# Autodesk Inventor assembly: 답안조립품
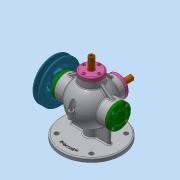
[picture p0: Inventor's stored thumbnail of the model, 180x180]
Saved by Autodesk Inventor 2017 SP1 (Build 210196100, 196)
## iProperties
Part Number: 답안조립품
Material: 일반
Document SubType Name: Assembly
Designer: MRC
Mass: 3733.58 g
Surface Area: 2584.17 cm^2
Volume: 938.795 cm^3
Density: 3.97699 g/cm^3
Author: MRC
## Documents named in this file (17)
- C:\Users\MRC\Desktop\620909V1003\답안조립품.iam
- C:\Users\MRC\Desktop\620909V1003\본체.ipt
- C:\Users\MRC\Desktop\620909V1003\V-벨트풀리.ipt
- C:\Users\MRC\Desktop\620909V1003\너트-M8x1.ipt
- C:\Users\MRC\Desktop\620909V1003\뒤커버.ipt
- C:\Users\MRC\Desktop\620909V1003\베어링- 6202.ipt
- C:\Users\MRC\Desktop\620909V1003\본체커버.ipt
- C:\Users\MRC\Desktop\620909V1003\볼트 M4x0.7.ipt
- C:\Users\MRC\Desktop\620909V1003\슬라이드 커버.ipt
- C:\Users\MRC\Desktop\620909V1003\슬라이드.ipt
- C:\Users\MRC\Desktop\620909V1003\앞커버.ipt
- C:\Users\MRC\Desktop\620909V1003\오일실.ipt
- C:\Users\MRC\Desktop\620909V1003\와셔 8x17.ipt
- C:\Users\MRC\Desktop\620909V1003\축.ipt
- C:\Users\MRC\Desktop\620909V1003\키-4x4.ipt
- C:\Users\MRC\Desktop\620909V1003\가변스프링1.ipt
- C:\Users\MRC\Desktop\620909V1003\가변스프링2.ipt
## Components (20 placed, 4 different names)
1. V-벨트풀리:1
2. 가변스프링1:1
3. 가변스프링2:1
4. M4x0.7x12:17
5. M4x0.7x12:2
6. M4x0.7x12:5
7. M4x0.7x12:6
8. M4x0.7x12:7
9. M4x0.7x12:4
10. M4x0.7x12:8
11. M4x0.7x12:9
12. M4x0.7x12:10
13. M4x0.7x12:1
14. M4x0.7x12:11
15. M4x0.7x12:12
16. M4x0.7x12:13
17. M4x0.7x12:3
18. M4x0.7x12:14
19. M4x0.7x12:15
20. M4x0.7x12:16
